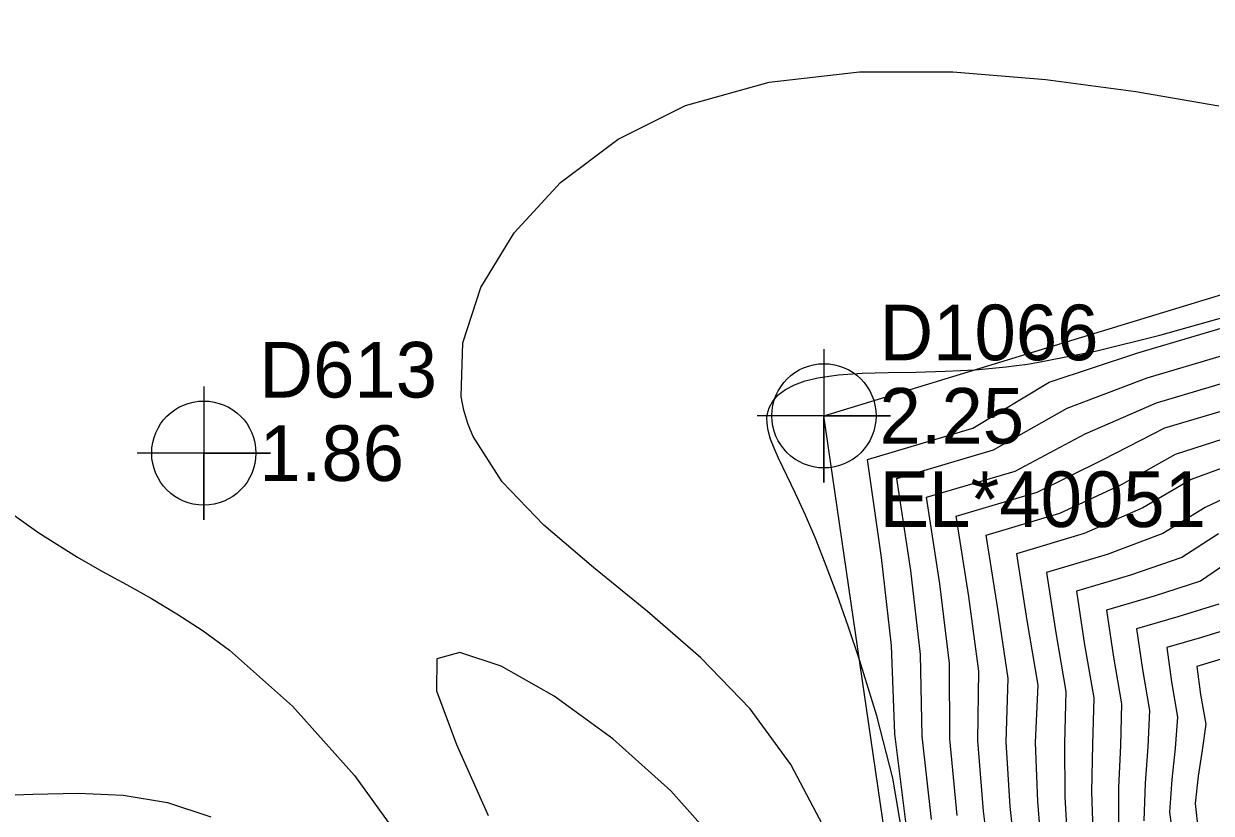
# Model space of a CAD drawing. Extents: x 2356077 to 2359823, y 225951 to 227822.
# Drawn here: x 2357294.1 to 2357347.5, y 226683.4 to 226718.9 of the extents above; entities that cross this region are included whole.
import ezdxf

# ---------------------------------------------------------------- set-up
doc = ezdxf.new("R2010")
doc.units = 0
for name, color, linetype in [('DTM Contours Major', 7, 'Continuous'), ('DTM Contours Minor', 7, 'Continuous'), ('Exist DTM Breakline', 7, 'Continuous'), ('Exist DTM Breakline Cogo Comment', 7, 'Continuous'), ('Exist DTM Breakline Cogo Elevation', 7, 'Continuous'), ('Exist DTM Breakline Cogo Number', 7, 'Continuous'), ('Exist DTM Breakline Cogo Point CELL', 7, 'Continuous'), ('Exist DTM Regular Point CELL', 7, 'Continuous'), ('Exist DTM Regular Point Cogo Elevation', 7, 'Continuous'), ('Exist DTM Regular Point Cogo Number', 7, 'Continuous')]:
    doc.layers.add(name, color=color, linetype=linetype)

msp = doc.modelspace()

# ---------------------------------------------------------------- linework, layer by layer
at = {"layer": 'DTM Contours Major'}
for points in [[(2357330.075, 226682.872), (2357328.628, 226685.605), (2357326.799, 226688.112), (2357324.589, 226690.398), (2357322.179, 226692.488), (2357319.758, 226694.455), (2357317.517, 226696.371), (2357315.647, 226698.311), (2357314.34, 226700.349), (2357314.215, 226700.64), (2357314.104, 226700.934), (2357314.008, 226701.231), (2357313.926, 226701.532), (2357313.859, 226701.837), (2357313.806, 226702.145), (2357313.871, 226704.561), (2357314.691, 226707.058), (2357316.185, 226709.506), (2357318.27, 226711.772), (2357320.865, 226713.725), (2357323.889, 226715.236), (2357327.661, 226716.288), (2357331.719, 226716.751), (2357335.916, 226716.751), (2357340.107, 226716.412), (2357344.146, 226715.86), (2357347.887, 226715.222)], [(2357337.693, 226680.388), (2357337.302, 226683.501), (2357337.051, 226686.679), (2357337.089, 226689.794), (2357336.642, 226693.162), (2357336.07, 226696.769), (2357339.711, 226697.847), (2357342.69, 226699.316), (2357345.455, 226700.742), (2357355.187, 226703.622)], [(2357293.135, 226697.199), (2357294.8, 226696.022), (2357296.545, 226694.923), (2357297.632, 226694.302), (2357298.739, 226693.691), (2357299.867, 226693.061), (2357301.016, 226692.382), (2357302.188, 226691.621), (2357303.384, 226690.75), (2357306.218, 226688.226), (2357309.005, 226685.105), (2357311.567, 226681.55)], [(2357348.49, 226694.817), (2357347.056, 226693.852), (2357344.972, 226693.18), (2357342.836, 226692.548), (2357343.152, 226690.431), (2357343.514, 226688.327), (2357343.456, 226686.458), (2357343.37, 226684.574), (2357343.373, 226682.645)]]:
    msp.add_lwpolyline(points, dxfattribs=at)
at = {"layer": 'DTM Contours Minor'}
for points in [[(2357333.819, 226682.911), (2357333.306, 226686.982), (2357333.164, 226690.955), (2357332.716, 226694.916), (2357332.075, 226699.321), (2357336.826, 226700.727), (2357340.261, 226702.798), (2357344.249, 226704.119), (2357356.207, 226707.658)], [(2357334.959, 226683.13), (2357334.54, 226686.877), (2357334.466, 226690.55), (2357334.026, 226694.322), (2357333.402, 226698.469), (2357337.748, 226699.755), (2357341.064, 226701.626), (2357344.663, 226702.997), (2357355.887, 226706.319)], [(2357334.277, 226678.799), (2357333.213, 226684.994), (2357332.498, 226687.787), (2357331.719, 226690.312), (2357331.212, 226691.827), (2357330.713, 226693.236), (2357330.225, 226694.538), (2357329.749, 226695.73), (2357329.289, 226696.812), (2357328.847, 226697.784), (2357328.081, 226699.372), (2357327.881, 226699.823), (2357327.722, 226700.24), (2357327.614, 226700.627), (2357327.58, 226700.811), (2357327.562, 226700.989), (2357327.559, 226701.161), (2357327.574, 226701.326), (2357327.605, 226701.486), (2357327.654, 226701.639), (2357327.819, 226701.944), (2357328.065, 226702.221), (2357328.392, 226702.467), (2357328.798, 226702.68), (2357329.283, 226702.856), (2357329.846, 226702.994), (2357330.776, 226703.125), (2357331.838, 226703.196), (2357333.008, 226703.23), (2357334.262, 226703.253), (2357335.575, 226703.288), (2357336.925, 226703.357), (2357337.385, 226703.393), (2357337.848, 226703.435), (2357338.316, 226703.486), (2357338.791, 226703.545), (2357339.275, 226703.612), (2357339.769, 226703.689), (2357342.393, 226704.205), (2357345.226, 226704.904), (2357348.17, 226705.727)], [(2357336.117, 226683.305), (2357335.785, 226686.76), (2357335.771, 226690.152), (2357335.335, 226693.734), (2357334.733, 226697.618), (2357338.717, 226698.797), (2357341.876, 226700.47), (2357345.075, 226701.874), (2357355.567, 226704.979)], [(2357338.808, 226680.838), (2357338.497, 226683.711), (2357338.32, 226686.621), (2357338.402, 226689.464), (2357337.946, 226692.601), (2357337.413, 226695.922), (2357340.731, 226696.904), (2357343.507, 226698.192), (2357345.934, 226699.561), (2357348.968, 226700.537)], [(2357349.224, 226699.368), (2357346.635, 226698.42), (2357344.469, 226697.143), (2357341.831, 226695.985), (2357338.784, 226695.083), (2357339.245, 226692.077), (2357339.743, 226689.177), (2357339.63, 226686.591), (2357339.724, 226683.939), (2357339.943, 226681.306)], [(2357349.321, 226698.128), (2357347.271, 226697.153), (2357345.371, 226695.988), (2357342.865, 226695.046), (2357340.133, 226694.237), (2357340.547, 226691.529), (2357341.001, 226688.888), (2357340.937, 226686.545), (2357340.959, 226684.156), (2357341.094, 226681.761)], [(2357347.878, 226695.975), (2357346.215, 226694.91), (2357343.915, 226694.112), (2357341.484, 226693.392), (2357341.85, 226690.98), (2357342.257, 226688.608), (2357342.201, 226686.504), (2357342.165, 226684.37), (2357342.231, 226682.208)], [(2357347.888, 226692.816), (2357346.035, 226692.25), (2357344.189, 226691.703), (2357344.456, 226689.878), (2357344.772, 226688.039), (2357344.699, 226686.401), (2357344.57, 226684.762), (2357344.518, 226683.065)], [(2357348.709, 226691.805), (2357347.104, 226691.322), (2357345.541, 226690.859), (2357345.76, 226689.32), (2357346.032, 226687.738), (2357345.928, 226686.332), (2357345.767, 226684.932), (2357345.669, 226683.467), (2357345.873, 226681.911)], [(2357325.548, 226681.83), (2357323.236, 226684.414), (2357320.62, 226686.751), (2357317.979, 226688.675), (2357315.593, 226690.025), (2357313.742, 226690.637), (2357312.704, 226690.348), (2357312.695, 226688.921), (2357313.584, 226686.497), (2357315.009, 226683.305)], [(2357348.188, 226690.398), (2357346.896, 226690.015), (2357347.065, 226688.758), (2357347.295, 226687.416), (2357347.143, 226686.251), (2357346.959, 226685.082), (2357346.825, 226683.846), (2357346.959, 226682.625)], [(2357292.52, 226684.201), (2357294.538, 226684.276), (2357296.568, 226684.315), (2357298.591, 226684.221), (2357300.589, 226683.898), (2357302.542, 226683.25)]]:
    msp.add_lwpolyline(points, dxfattribs=at)
at = {"layer": 'Exist DTM Breakline'}
for points in [[(2357330.12, 226701.283), (2357367.055, 226712.54), (2357393.899, 226723.249), (2357392.689, 226749.681), (2357393.341, 226779.571), (2357395.626, 226793.612)], [(2357281.817, 226596.55), (2357301.263, 226620.711), (2357322.988, 226644.434), (2357334.581, 226670.667), (2357330.12, 226701.283)]]:
    msp.add_lwpolyline(points, dxfattribs=at)
at = {"layer": 'Exist DTM Breakline Cogo Point CELL'}
msp.add_lwpolyline([(2357330.12, 226704.283), (2357330.12, 226698.283), (2357330.12, 226701.283), (2357333.12, 226701.283), (2357327.12, 226701.283)], dxfattribs=at)
msp.add_circle((2357330.12, 226701.283), 2.344, dxfattribs=at)
at = {"layer": 'Exist DTM Regular Point CELL'}
msp.add_lwpolyline([(2357302.223, 226702.605), (2357302.223, 226696.605), (2357302.223, 226699.605), (2357305.223, 226699.605), (2357299.223, 226699.605)], dxfattribs=at)
msp.add_circle((2357302.223, 226699.605), 2.344, dxfattribs=at)

# ---------------------------------------------------------------- texts
at = {"layer": 'Exist DTM Breakline Cogo Comment'}
msp.add_text('EL*40051', height=2.5, dxfattribs=at).set_placement((2357332.62, 226696.283))
at = {"layer": 'Exist DTM Breakline Cogo Elevation'}
msp.add_text('2.25', height=2.5, dxfattribs=at).set_placement((2357332.62, 226700.033))
at = {"layer": 'Exist DTM Breakline Cogo Number'}
msp.add_text('D1066', height=2.5, dxfattribs=at).set_placement((2357332.62, 226703.783))
at = {"layer": 'Exist DTM Regular Point Cogo Elevation'}
msp.add_text('1.86', height=2.5, dxfattribs=at).set_placement((2357304.723, 226698.355))
at = {"layer": 'Exist DTM Regular Point Cogo Number'}
msp.add_text('D613', height=2.5, dxfattribs=at).set_placement((2357304.723, 226702.105))

doc.saveas('drawing.dxf')
